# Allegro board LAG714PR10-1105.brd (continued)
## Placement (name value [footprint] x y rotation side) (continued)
PCG123  22U_0603_6.3V6M  [C_0603]  128.2 101.02 0 top
PCG124  22U_0603_6.3V6M  [C_0603]  126.74 101.12 180 top
PCG125  22U_0603_6.3V6M  [C_0603]  134.78 126.17 90 top
PCG126  22U_0603_6.3V6M  [C_0603]  122.56 90.89 270 top
PCG127  22U_0603_6.3V6M  [C_0603]  126.73 106.2 180 top
PCG128  22U_0603_6.3V6M  [C_0603]  123.83 93.31 270 top
PCG129  22U_0603_6.3V6M  [C_0603]  123.83 90.89 270 top
PCG130  22U_0603_6.3V6M  [C_0603]  130.3 89.59 180 top
PCG131  22U_0603_6.3V6M  [C_0603]  122.56 93.31 270 top
PCG132  22U_0603_6.3V6M  [C_0603]  128.2 103.56 0 top
PCG133  22U_0603_6.3V6M  [C_0603]  126.73 103.66 180 top
PCG134  0.47U_0201_6.3V6K  [C_0201]  127.07 90.54 90 top
PCG135  0.47U_0201_6.3V6K  [C_0201]  126.05 89.92 270 top
PCG136  0.47U_0201_6.3V6K  [C_0201]  124.75 95.97 180 top
PCG137  0.47U_0201_6.3V6K  [C_0201]  126.05 90.54 90 top
PCG138  1U_0201_6.3V6M  [C_0201]  130.58 99.91 0 top
PCG139  1U_0201_6.3V6M  [C_0201]  124.75 98.64 180 top
PCG140  1U_0201_6.3V6M  [C_0201]  124.75 97.31 180 top
PCG141  1U_0201_6.3V6M  [C_0201]  128.08 89.92 270 top
PCG142  1U_0201_6.3V6M  [C_0201]  127.07 89.92 270 top
PCG143  1U_0201_6.3V6M  [C_0201]  130.65 97.94 0 top
PCG144  1U_0201_6.3V6M  [C_0201]  131.69 93.59 0 top
PCG145  1U_0201_6.3V6M  [C_0201]  131.7 92.86 0 top
PCG146  1U_0201_6.3V6M  [C_0201]  128.11 90.54 90 top
PCG147  10U_0402_6.3V6M  [C_0402]  132.05 92.02 270 top
PCG148  10U_0402_6.3V6M  [C_0402]  133.89 95.23 90 top
PCG171  220U 2V Y D2  [C_D2]  135.29 122.21 90 bottom
PCG172  220U 2V Y D2  [C_D2]  133.23 117.79 0 bottom
PCH01  0.1U_0402_25V6  [C_0402]  175.07 56.23 90 bottom
PCH02  2200P_0402_50V7K  [C_0402]  174.18 56.23 90 bottom
PCH03  10U_0805_25V6K~D  [C_0805]  170.96 54.49 90 bottom
PCH04  10U_0805_25V6K~D  [C_0805]  170.96 54.49 90 top
PCH05  22U_0603_6.3V6M  [C_0603]  153.39 56.62 90 bottom
PCH06  22U_0603_6.3V6M  [C_0603]  154.59 56.62 90 bottom
PCH07  22U_0603_6.3V6M  [C_0603]  154.59 52.87 270 bottom
PCH08  22U_0603_6.3V6M  [C_0603]  153.39 52.87 270 bottom
PCH09  0.1U_0402_25V6  [C_0402]  170.51 53.48 0 top
PCH10  1U_0402_10V6K  [C_0402]  168.63 51.87 270 top
PCH11  1U_0402_10V6K  [C_0402]  166.79 51.87 270 bottom
PCH12  0.1U_0402_10V6K  [C_0402]  164.63 50.96 90 bottom
PCH13  680P_0603_50V7K  [C_0603]  167.17 55.49 0 top
PCH14  330P_0402_50V7K  [C_0402]  170.14 50.1 0 bottom
PCH15  1000P_0402_50V7K  [C_0402]  173.27 56.23 90 bottom
PCH16  1000P_0402_50V7K  [C_0402]  172.37 56.25 90 bottom
PCI01  10U_0805_25V6K  [C_0805]  164.5 74.17 270 bottom
PCI02  10U_0805_25V6K  [C_0805]  166.21 74.17 270 bottom
PCI03  10U_0805_25V6K  [C_0805]  164.5 74.17 270 top
PCI04  10U_0805_25V6K  [C_0805]  166.21 74.17 270 top
PCI05  1000P_0402_50V7K  [C_0402]  163.17 73.4 270 bottom
PCI06  0.1U_0402_25V6  [C_0402]  162.28 73.4 270 bottom
PCI07  2200P_0402_50V7K  [C_0402]  161.39 73.38 270 bottom
PCI08  1000P_0402_50V7K  [C_0402]  167.53 74.02 270 bottom
PCI09  0.22U_0603_25V7K  [C_0603]  165.71 75.8 180 bottom
PCI10  1U_0402_16V6K  [C_0402]  164.32 78.09 0 bottom
PCI11  1U_0402_16V6K  [C_0402]  165.13 79.87 270 bottom
PCI12  680P_0603_50V8J  [C_0603]  158.25 76.64 0 top
PCI13  33U_D2_25VM_R40M  [C_EEFCX1E330R]  163.99 83.58 270 bottom
PCI14  33U_25V_M  [C_6P3X4P5-NPM]  163.99 83.98 90 bottom
PCI21  0.1U_0402_25V6  [C_0402]  160.24 93.87 180 bottom
PCI22  2200P_0402_50V7K  [C_0402]  160.26 92.96 180 bottom
PCI23  10U_0805_25V6K  [C_0805]  161.68 93.51 0 bottom
PCI24  10U_0805_25V6K  [C_0805]  161.68 95.23 0 bottom
PCI25  10U_0805_25V6K  [C_0805]  161.68 93.51 0 top
PCI26  10U_0805_25V6K  [C_0805]  161.68 95.23 0 top
PCI27  1000P_0402_50V7K  [C_0402]  160.26 95.71 180 bottom
PCI28  1000P_0402_50V7K  [C_0402]  160.26 94.78 180 bottom
PCI29  0.22U_0603_25V7K  [C_0603]  164.31 97.26 180 bottom
PCI30  1U_0402_16V6K  [C_0402]  162.95 99.6 0 bottom
PCI31  1U_0402_16V6K  [C_0402]  163.8 101.39 270 bottom
PCI32  680P_0603_50V8J  [C_0603]  158.07 102.89 270 top
PCI101  22U_0603_6.3V6M  [C_0603]  125.99 82.39 0 top
PCI102  22U_0603_6.3V6M  [C_0603]  122.75 81.37 0 top
PCI103  22U_0603_6.3V6M  [C_0603]  130.15 80.02 270 top
PCI104  22U_0603_6.3V6M  [C_0603]  130.24 81.12 180 top
PCI105  22U_0603_6.3V6M  [C_0603]  128.93 80.02 270 top
PCI106  22U_0603_6.3V6M  [C_0603]  128.53 85.02 180 top
PCI107  22U_0603_6.3V6M  [C_0603]  130.05 76.99 270 top
PCI108  22U_0603_6.3V6M  [C_0603]  128.78 76.99 270 top
PCI109  22U_0603_6.3V6M  [C_0603]  124.27 83.02 90 top
PCI110  22U_0603_6.3V6M  [C_0603]  123 83.02 90 top
PCI111  22U_0603_6.3V6M  [C_0603]  127.71 80.02 270 top
PCI112  22U_0603_6.3V6M  [C_0603]  126.49 80.02 270 top
PCI113  22U_0603_6.3V6M  [C_0603]  125.27 80.02 270 top
PCI114  22U_0603_6.3V6M  [C_0603]  127.51 76.99 270 top
PCI115  22U_0603_6.3V6M  [C_0603]  124.97 76.99 270 top
PCI116  22U_0603_6.3V6M  [C_0603]  126.24 76.99 270 top
PCI117  22U_0603_6.3V6M  [C_0603]  122.75 78.83 0 top
PCI118  22U_0603_6.3V6M  [C_0603]  122.75 80.1 0 top
PCI119  22U_0603_6.3V6M  [C_0603]  149.58 87.74 0 top
PCI120  22U_0603_6.3V6M  [C_0603]  131.32 76.99 270 top
PCI121  22U_0603_6.3V6M  [C_0603]  126.05 85.43 90 top
PCI122  22U_0603_6.3V6M  [C_0603]  125.35 81.12 0 top
PCI123  22U_0603_6.3V6M  [C_0603]  123.76 77.69 270 top
PCI124  22U_0603_6.3V6M  [C_0603]  149.58 86.47 0 top
PCI125  22U_0603_6.3V6M  [C_0603]  122.56 77.69 270 top
PCI126  22U_0603_6.3V6M  [C_0603]  149.58 85.2 0 top
PCI127  22U_0603_6.3V6M  [C_0603]  149.58 89.02 0 top
PCI128  22U_0603_6.3V6M  [C_0603]  149.58 83.93 0 top
PCI129  1U_0201_6.3V6M  [C_0201]  128.08 80.82 90 top
PCI130  1U_0201_6.3V6M  [C_0201]  146.72 87.66 270 top
PCI131  1U_0201_6.3V6M  [C_0201]  132.27 79.43 90 top
PCI132  1U_0201_6.3V6M  [C_0201]  129.69 77.81 0 top
PCI133  1U_0201_6.3V6M  [C_0201]  122.05 83.43 90 top
PCI134  1U_0201_6.3V6M  [C_0201]  120.55 79.15 0 top
PCI135  1U_0201_6.3V6M  [C_0201]  146.08 91.22 270 top
PCI136  1U_0201_6.3V6M  [C_0201]  145.45 91.22 270 top
PCI137  1U_0201_6.3V6M  [C_0201]  147.35 87.66 270 top
PCI138  1U_0201_6.3V6M  [C_0201]  144.18 88.86 90 top
PCI139  1U_0201_6.3V6M  [C_0201]  120.48 78.33 270 top
PCI140  1U_0201_6.3V6M  [C_0201]  121.13 80.16 180 top
PCI141  1U_0201_6.3V6M  [C_0201]  126.46 77.81 0 top
PCI142  1U_0201_6.3V6M  [C_0201]  120.55 80.99 0 top
PCI143  1U_0201_6.3V6M  [C_0201]  128.04 77.81 0 top
PCI144  1U_0201_6.3V6M  [C_0201]  124.87 77.81 0 top
PCI145  1U_0201_6.3V6M  [C_0201]  144.18 87.66 270 top
PCI146  1U_0201_6.3V6M  [C_0201]  144.18 91.22 270 top
PCI147  1U_0201_6.3V6M  [C_0201]  144.18 94.74 270 top
PCI148  1U_0201_6.3V6M  [C_0201]  144.81 92.41 90 top
PCI149  1U_0201_6.3V6M  [C_0201]  145.45 87.66 270 top
PCI150  1U_0201_6.3V6M  [C_0201]  146.08 87.66 270 top
PCI151  1U_0201_6.3V6M  [C_0201]  144.81 87.66 270 top
PCI152  1U_0201_6.3V6M  [C_0201]  147.99 87.66 270 top
PCI153  1U_0201_6.3V6M  [C_0201]  146.72 88.86 90 top
PCI154  1U_0201_6.3V6M  [C_0201]  146.08 88.86 90 top
PCI155  1U_0201_6.3V6M  [C_0201]  145.45 88.86 90 top
PCI156  1U_0201_6.3V6M  [C_0201]  148.62 87.66 270 top
PCI157  1U_0201_6.3V6M  [C_0201]  133.51 81.3 90 top
PCI158  1U_0201_6.3V6M  [C_0201]  144.18 92.41 90 top
PCI159  1U_0201_6.3V6M  [C_0201]  144.81 88.86 90 top
PCI160  1U_0201_6.3V6M  [C_0201]  132.27 77.34 270 top
PCI161  1U_0201_6.3V6M  [C_0201]  133.49 77.37 0 top
PCI162  1U_0201_6.3V6M  [C_0201]  144.81 91.22 270 top
PCI163  1U_0201_6.3V6M  [C_0201]  127.51 80.82 90 top
PCI164  10U_0402_6.3V6M  [C_0402]  132.11 81.92 270 top
PCI165  10U_0402_6.3V6M  [C_0402]  132.11 82.79 90 top
PCI171  220U 2V Y D2  [C_D2]  152.47 90.15 0 bottom
PCI172  330U_D2_2V_Y  [C_D2]  145.96 95.28 90 bottom
PCI173  220U 2V Y D2  [C_D2]  148.05 90.76 270 bottom
PCM01  0.1U_0402_25V6  [C_0402]  96.59 139.63 270 bottom
PCM02  2200P_0402_50V7K  [C_0402]  95.7 139.63 270 bottom
PCM03  4.7U_0805_25V6K  [C_0805]  94.3 140.53 270 top
PCM04  4.7U_0805_25V6K  [C_0805]  94.3 140.53 270 bottom
PCM05  22U_0603_6.3V6M  [C_0603]  83.92 131.5 180 top
PCM06  22U_0603_6.3V6M  [C_0603]  83.92 130.23 180 top
PCM07  22U_0603_6.3V6M  [C_0603]  87.73 131.5 0 top
PCM08  22U_0603_6.3V6M  [C_0603]  83.92 131.5 180 bottom
PCM09  22U_0603_6.3V6M  [C_0603]  87.73 131.5 0 bottom
PCM10  22U_0603_6.3V6M  [C_0603]  83.92 130.23 180 bottom
PCM11  680P_0402_50V7K  [C_0402]  90.51 138.87 0 top
PCM12  0.1U_0402_10V7K  [C_0402]  93.13 136.6 270 bottom
PCM13  1U_0603_10V6K  [C_0603]  91.6 132.65 180 bottom
PCM14  1U_0603_10V6K  [C_0603]  91.6 131.42 180 bottom
PCM15  0.1U_0402_10V7K  [C_0402]  95.47 129.61 270 bottom
PCM16  0.1U_0402_10V7K  [C_0402]  96.36 129.61 270 bottom
PCM17  220P_0402_25V8J  [C_0402]  98.52 129.78 90 bottom
PCM18  .1U_0402_16V7K  [C_0402]  98.51 131.57 0 bottom
PCM19  0.033U_0402_16V7K  [C_0402]  98.51 132.52 0 bottom
PCM20  10U_0603_6.3V6M  [C_0603]  98.9 133.76 90 top
PCM21  10U_0603_6.3V6M  [C_0603]  98.87 134.08 90 bottom
PCM22  1000P_0402_50V7K  [C_0402]  96.59 139.63 270 top
PCM23  1000P_0402_50V7K  [C_0402]  95.7 139.63 270 top
PCZ01  8200P_0402_25V7K  [C_0402]  155.85 114.98 0 top
PCZ02  2200P_0402_50V7K  [C_0402]  158.53 115.6 90 bottom
PCZ03  15P_0402_50V8J  [C_0402]  155.85 115.87 0 top
PCZ04  1000P_0402_50V7K  [C_0402]  156.76 112.82 180 bottom
PCZ05  1000P_0402_50V7K  [C_0402]  154.42 115.61 180 top
PCZ06  1000P_0402_50V7K  [C_0402]  157.67 112.81 90 bottom
PCZ07  2200P_0402_25V7K  [C_0402]  156.76 114.6 180 bottom
PCZ08  0.01U_0402_25V7K  [C_0402]  155.86 115.6 90 bottom
PCZ09  1200P_0402_50V7K  [C_0402]  156.75 115.6 90 bottom
PCZ10  1000P_0402_50V7K  [C_0402]  155.28 110.98 0 bottom
PCZ11  3300P_0402_25V7K  [C_0402]  156.18 110.07 90 top
PCZ12  470P_0402_50V7K  [C_0402]  154.42 116.5 180 top
PCZ13  470P_0402_50V7K  [C_0402]  153.39 107.92 90 bottom
PCZ14  470P_0402_50V7K  [C_0402]  151.86 111.47 90 top
PCZ15  15P_0402_50V8J  [C_0402]  153.4 109.71 180 top
PCZ16  2200P_0402_50V7K  [C_0402]  152.5 107.92 90 top
PCZ17  820P_0402_50V7K  [C_0402]  151.62 109.71 180 bottom
PCZ18  100P_0402_50V8J  [C_0402]  151.62 108.82 180 bottom
PCZ19  0.1U_0402_25V6  [C_0402]  150.47 111.47 90 top
PCZ20  0.1U_0402_25V6  [C_0402]  149.84 109.71 180 top
PCZ21  0.1U_0402_25V6  [C_0402]  149.84 108.82 180 bottom
PCZ22  1000P_0402_50V7K  [C_0402]  149.13 111.47 90 top
PCZ23  0.01U_0402_50V7K  [C_0402]  147.35 110.54 270 bottom
PCZ24  0.1U_0402_25V6  [C_0402]  154.59 120.04 90 top
PCZ25  470P_0402_50V7K  [C_0402]  151.04 118.74 270 top
PCZ26  0.022U_0402_16V7K  [C_0402]  150.03 120.06 180 top
PCZ27  5600P_0402_25V7K  [C_0402]  150.03 120.03 180 bottom
PCZ28  3300P_0402_50V7-K  [C_0402]  146.15 118.14 90 bottom
PCZ29  1000P_0402_50V7K  [C_0402]  146.47 120.26 270 top
PCZ30  150P_0402_50V8J  [C_0402]  147.18 121.22 180 top
PCZ31  0.015U_0402_25V7K  [C_0402]  148.12 120.38 90 top
PCZ32  1000P_0402_50V7K  [C_0402]  149.26 118.74 270 top
PCZ33  2200P_0402_50V7K  [C_0402]  150.15 118.74 270 top
PCZ34  1U_0603_10V6K  [C_0603]  145.64 112.25 180 bottom
PCZ35  1000P_0402_50V7K  [C_0402]  144.67 117.58 0 top
PCZ36  1000P_0402_50V7K  [C_0402]  145.59 116.69 180 top
PD1  -  [TVNST52302AB0_SOT523-3]  82.08 143.38 180 top
PD2  -  [BAV99W_SC70-3]  89.28 148.25 0 top
PD3  -  [BAV99W_SC70-3]  90.61 143.29 180 top
PD5  -  [TVNST52302AB0_SOT523-3]  161.83 36.32 180 top
PD6  -  [TVNST52302AB0_SOT523-3]  167.29 38.35 0 top
PD501  -  [SDMK0340L-7-F_SOD323-2]  116.17 142.04 180 bottom
PDB01  -  [LRB715FT1G_SOT323-3]  193.78 43.87 90 bottom
PHZ01  100K_0402_1%_B25/50 4250K  [R_0402]  158.53 65.32 90 bottom
PHZ02  220K_0402_5%_B25/50 4700K  [R_0402]  151.04 81.02 270 bottom
PHZ03  100K_0402_1%_B25/50 4250K  [R_0402]  143.24 120.96 180 bottom
PHZ04  100K_0402_1%_B25/50 4250K  [R_0402]  161.21 80.81 180 bottom
PHZ05  100K_0402_1%_B25/50 4250K  [R_0402]  138.53 136.15 270 bottom
PJP1  JUMP_43X79  [JUMP_43X79-NPM]  95.47 144.96 0 top
PJP2  -  [JUMP_43X79]  76.24 145.17 180 bottom
PJP3  JUMP_43X79  [JUMP_43X79-NPM]  176.21 45.23 180 bottom
PJP301  -  [JUMP_43X39]  101.05 140.01 0 bottom
PJP302  -  [JUMP_43X118]  115.83 131.44 270 top
PJP501  -  [JUMP_43X79]  152.84 142.7 270 top
PJP502  -  [JUMP_43X118]  158.28 124.18 270 bottom
PJP1801  -  [JUMP_43X39]  171.03 45.43 90 top
PJP1802  -  [JUMP_43X79]  153.49 46.65 180 bottom
PJP2501  -  [JUMP_43X39]  48.73 26.1 0 bottom
PJP2502  -  [JUMP_43X39]  52.74 36.71 90 top
PJPA01  -  [JUMP_43X39]  167.04 68.33 270 bottom
PJPB01  JUMP_43X118  [JUMP_43X118-NPM]  186.81 55.68 0 bottom
PJPDC1  ACES_50458-00601-001  [ACES_50458-00601-001_6P-T]  81.2 144.15 0 bottom
PJPG01  -  [JUMP_43X79]  142.12 142.24 270 top
PJPH01  -  [JUMP_43X39]  177.4 56.89 180 bottom
PJPH02  -  [JUMP_43X118]  154.34 56.28 90 top
PJPI01  JUMP_43X79  [JUMP_43X79-NPM]  170 81.34 180 bottom
PJPM01  -  [JUMP_43X39]  97.76 141.16 180 top
PJPM02  -  [JUMP_43X118]  87.03 129.51 270 bottom
PJPM03  -  [JUMP_43X39]  98.97 132.34 270 top
PL1  5A Z150 20M 1210_2P  [5A_Z150_1210_2P]  94.65 144.86 0 top
PL2  5A Z150 20M 1210_2P  [5A_Z150_1210_2P-NPM]  77.05 145.17 180 bottom
PL3  BLM15AG102SN1D_2P  [MURAT_BLM15AG102SN1D_2P]  84.41 144.71 180 top
PL4  5A Z150 20M 1210_2P  [5A_Z150_1210_2P]  177.05 45.17 180 bottom
PL301  1.5UH_9A_20%_7X7X3_M  [L_7X7X3_M_2P]  106.09 132.99 0 bottom
PL311  5A Z80 20M 0805  [TAI-T_HCB2012KF-121T50_2P]  100.66 137.98 0 bottom
PL501  1.5UH_9A_20%_7X7X3_M  [L_7X7X3_M_2P]  158.28 133.44 270 bottom
PL511  5A Z150 20M 1210_2P  [5A_Z150_1210_2P]  149.21 142.68 270 top
PL1801  1UH_6.6A_20%_5X5X3_M  [L_5X5X3_M_2P]  161.98 46.78 180 bottom
PL1811  5A_Z120_25M_0805_2P  [TAI-T_HCB2012KF-121T50_2P]  171.2 44.89 90 bottom
PLA01  0.47UH_MMD05CZR47M_12A_20%  [L_5X5X3_M]  162.04 61.95 180 bottom
PLB01  4.7UH_5.5A_20%_7X7X3_M  [L_7X7X3_M_2P]  182.11 43.81 90 bottom
PLB02  5A Z150 20M 1210_2P  [5A_Z150_1210_2P]  186.01 55.68 0 bottom
PLG01  0.15UH_MMD-06DZER15MEM1L__36A_20%  [L_7X7X4_M]  145.7 125.21 180 bottom
PLG11  5A Z150 20M 1210_2P  [5A_Z150_1210_2P]  145.75 142.68 270 top
PLH01  1UH_11A_20%_7X7X3_M  [L_7X7X3_M_2P]  163.18 54.84 180 bottom
PLH11  5A Z80 20M 0805  [TAI-T_HCB2012KF-121T50_2P]  177.36 54.87 180 bottom
PLI01  0.15UH_MMD-06DZER15MEM1L__36A_20%  [L_7X7X4_M]  158.49 83.98 180 bottom
PLI02  0.15UH_MMD-06DZER15MEM1L__36A_20%  [L_7X7X4_M]  152.12 100.79 270 bottom
PLI11  5A Z150 20M 1210_2P  [5A_Z150_1210_2P]  170.8 81.34 180 bottom
PLM01  1UH_11A_20%_7X7X3_M  [L_7X7X3_M_2P]  85.92 134.08 90 bottom
PLM11  5A Z80 20M 0805  [TAI-T_HCB2012KF-121T50_2P]  98.03 140.96 180 bottom
PQ1  -  [FDV301N-G_SOT23-3]  82.58 147.26 270 top
PQ2  -  [MMST3904-7-F_SOT323-3]  87.18 143.2 0 top
PQ11  2N7002KW_SOT323-3  [DMN65D8LW-7_SOT323-3]  27.02 60.38 90 top
PQ12  2N7002KDW_SOT363-6  [DMN65D8LDW-7_SOT363-6]  118.12 142.52 180 top
PQ13  2N7002KDW_SOT363-6  [DMN65D8LDW-7_SOT363-6]  120.35 140.03 0 top
PQA01  PE642DT_PDFN8-10  [AON7934_DFN3X3A8-10]  164.67 64.03 0 bottom
PQB01  AON7408L_DFN8-5  [AON7702L_DFN8-5]  186.64 49.25 90 bottom
PQB02  AON7506_DFN33-8-5  [AON7702L_DFN8-5]  189.51 47.4 270 bottom
PQB03  2N7002KW_SOT323-3  [DMN65D8LW-7_SOT323-3]  181.3 66.43 90 top
PQB04  2N7002KW_SOT323-3  [DMN65D8LW-7_SOT323-3]  204.32 56.95 90 top
PQB05  -  [RUM002N02GT2L_VMT3]  205.33 49.36 270 top
PQB06  -  [RUM002N02GT2L_VMT3]  206.67 47.62 270 top
PQB07  -  [LTC015EUBFS8TL_UMT3F]  175.42 35.71 180 top
PQB08  -  [LMUN5113T1G_SOT323-3]  171.55 36.38 270 top
PQB11  -  [TPCA8059-H_PPAK56-8-5]  180.2 59.63 90 top
PQB12  -  [TPCA8059-H_PPAK56-8-5]  181.96 62.25 270 top
PQB13  -  [TPCA8059-H_PPAK56-8-5]  183.76 52.76 180 bottom
PQM01  PE642DT_PDFN8-10  [AON7934_DFN3X3A8-10]  90.68 141.42 0 bottom
PR1  33_0402_5%  [R_0402]  86.72 148.22 0 top
PR3  100K_0402_1%  [R_0402]  86.72 147.26 0 top
PR4  10K_0402_1%  [R_0402]  88.93 145.17 270 top
PR5  2.2K_0402_5%  [R_0402]  87.64 149.17 180 top
PR6  15K_0402_1%  [R_0402]  87.64 146.31 180 top
PR7  100K_0402_1%  [R_0402]  88.35 142.93 0 top
PR31  0_0402_5%  [R_0402]  121.95 138.16 90 top
PR32  3.3K_1206_5%  [R_1206]  123.35 142.88 270 top
PR33  10K_0402_1%  [R_0402]  118.87 138.77 90 top
PR34  1M_0402_1%  [R_0402]  121.78 143.84 180 top
PR35  0_0402_5%  [R_0402]  120.23 138.18 0 top
PR36  1M_0402_1%  [R_0402]  118.41 143.82 180 top
PR37  100_0402_5%  [R_0402]  163.23 37.85 270 top
PR38  1M_0402_1%  [R_0402]  120.86 142.95 0 top
PR39  200_0402_5%  [R_0402]  164.88 37.85 270 top
PR40  100K_0402_1%  [R_0402]  117.1 139.67 180 top
PR41  10K_0402_1%  [R_0402]  165.77 36.94 90 top
PR42  100_0402_5%  [R_0402]  160.44 37.85 270 top
PR43  100K_0402_1%  [R_0402]  30.13 59.8 90 top
PR44  1M_0402_1%  [R_0402]  115.85 143.82 0 top
PR45  1M_0402_1%  [R_0402]  121.14 139.07 180 top
PR301  0_0603_5%  [R0603_0OHM]  104.69 137.49 270 bottom
PR302  499K_0402_1%  [R_0402]  109.25 142.48 90 bottom
PR303  150K_0402_1%  [R_0402]  110.14 142.48 90 bottom
PR304  10K_0402_1%  [R_0402]  109.58 141.03 180 top
PR305  4.7_1206_5%  [R_1206]  106.71 135.38 90 top
PR306  1K_0402_5%  [R_0402]  113.03 138.5 180 bottom
PR307  150K_0402_1%  [R_0402]  111.24 138.48 90 bottom
PR308  150K_0402_1%  [R_0402]  112.11 140.28 0 bottom
PR501  0_0603_5%  [R0603_0OHM]  155.18 137.1 270 bottom
PR502  0_0402_5%  [R0402_0OHM]  111.46 141.21 0 bottom
PR503  0_0402_5%  [R0402_0OHM]  161.39 139.11 90 bottom
PR504  10K_0402_1%  [R_0402]  158.94 141.86 270 bottom
PR505  4.7_1206_5%  [R_1206]  156.88 133.85 90 top
PR506  2.2K_0402_5%  [R_0402]  163.18 140.08 180 bottom
PR507  0_0402_5%  [R0402_0OHM]  115.27 143.31 0 bottom
PR508  1M_0402_5%  [R_0402]  112.38 142.93 180 bottom
PR509  1K_0402_5%  [R_0402]  163.19 137.44 180 bottom
PR510  150K_0402_1%  [R_0402]  161.4 137.41 90 bottom
PR511  150K_0402_1%  [R_0402]  162.28 139.15 0 bottom
PR1801  0_0402_5%  [R0402_0OHM]  166.8 49.38 180 top
PR1802  1M_0402_5%  [R_0402]  165.88 49.38 0 bottom
PR1803  100K_0402_5%  [R_0402]  164.75 48.61 270 top
PR1804  4.7_1206_5%  [R_1206]  162.21 48.17 270 top
PR1805  10K_0402_1%  [R_0402]  168.46 49.38 180 bottom
PR1807  20K_0402_1%  [R_0402]  170.16 48.24 180 bottom
PR2501  0_0402_5%  [R0402_0OHM]  57.21 27.62 180 bottom
PR2502  21.5K_0402_1%  [R_0402]  53.65 36.22 0 bottom
PR2503  10K_0402_1%  [R_0402]  55.36 36.07 270 bottom
PR2504  2.2_0402_1%  [R_0402]  49.95 30.61 270 bottom
PRA01  2.2_0603_5%  [R_0603]  171.74 62.78 180 bottom
PRA02  4.7_1206_5%  [R_1206]  162.21 62.97 270 top
PRB01  0.01_1206_1%  [R_1206_4P]  177.01 52.67 270 bottom
PRB02  0.01_1206_1%  [R_1206_4P]  187.61 56.29 180 top
PRB03  3M_0402_5%  [R_0402]  183.6 63.81 90 top
PRB04  0_0402_5%  [R_0402]  179.7 58.07 0 top
PRB05  0_0402_5%  [R0402_0OHM]  202.22 56.14 270 bottom
PRB06  2_0402_5%  [R_0402]  201.33 56.14 270 bottom
PRB07  4.02K_0402_1%  [R_0402]  179.85 66.12 180 top
PRB08  4.02K_0402_1%  [R_0402]  182.81 63.8 90 top
PRB09  392K_0402_1%  [R_0402]  204.96 55.24 180 top
PRB10  100_0402_1%  [R_0402]  198.64 55.32 270 bottom
PRB11  53.6K_0402_1%  [R_0402]  204.05 54.35 0 bottom
PRB12  0_0603_5%  [R0603_0OHM]  181.39 53.84 180 top
PRB13  100K_0402_1%  [R_0402]  204.96 53.27 180 bottom
PRB14  158K_0402_1%  [R_0402]  204.05 53.27 0 top
PRB15  0_0603_5%  [R0603_0OHM]  196.63 53.91 180 bottom
PRB16  0_0603_5%  [R_0603]  196.63 52.64 180 bottom
PRB17  0_0402_5%  [R0402_0OHM]  204.96 52.38 180 bottom
PRB18  0_0402_5%  [R0402_0OHM]  204.96 51.49 180 bottom
PRB19  0_0402_5%  [R_0402]  204.96 50.6 180 bottom
PRB20  1K_0402_1%  [R_0402]  204.96 49.72 180 bottom
PRB21  4.7_0402_5%  [R_0402]  196.41 49.44 90 bottom
PRB22  4.7_1206_5%  [R_1206]  186.53 49.4 270 top
PRB23  0_0402_5%  [R0402_0OHM]  204.96 48.83 180 bottom
PRB24  10.5K_0402_1%  [R_0402]  204.05 47.94 0 bottom
PRB25  100K_0402_1%  [R_0402]  197.65 46.43 270 bottom
PRB26  0_0402_5%  [R0402_0OHM]  197.63 45.52 0 top
PRB27  10_1206_5%  [R_1206]  193.77 46.16 0 bottom
PRB28  0_0603_5%  [R_0603]  172.06 38.29 0 top
PRB29  10K_0402_5%  [R_0402]  204.96 50.6 180 top
PRB30  10K_0402_5%  [R_0402]  203.68 46.27 90 top
PRB31  160K_0402_1%  [R_0402]  203.79 47.95 0 top
PRB32  200K_0402_1%  [R_0402]  198.14 48.71 270 top
PRB33  200K_0402_1%  [R_0402]  199 48.71 0 top
PRB34  2_0402_5%  [R_0402]  199.3 45.51 90 bottom
PRB35  75K_0402_1%  [R_0402]  198.47 46.43 270 bottom
PRB36  66.5K_0402_1%  [R_0402]  200.77 48.71 0 top
PRB37  182K_0402_1%  [R_0402]  203.45 46.43 0 bottom
PRB38  100_0402_1%  [R_0402]  202.6 46.43 270 bottom
PRB39  102K_0402_1%  [R_0402]  201.81 46.44 270 bottom
PRB40  10K_0402_1%  [R_0402]  200.85 45.52 90 bottom
PRB41  0_0402_5%  [R0402_0OHM]  200.07 45.51 90 bottom
PRB42  10K_0402_1%  [R_0402]  200.94 45.52 0 top
PRB43  1M_0402_1%  [R_0402]  184.36 64.52 0 top
PRC01  0.0002_0805_5%  [R_0805]  124.46 85.56 90 top
PRC02  0.0002_0805_5%  [R_0805]  130.01 88.32 270 top
PRC03  0.0002_0805_5%  [R_0805]  129.99 83.49 90 top
PRC04  SOLDER_0603  [SOLDER_PREFORMS_0603-NPM]  124.49 85.75 90 top
PRC05  SOLDER_0603  [SOLDER_PREFORMS_0603-NPM]  129.98 88.13 270 top
PRC06  SOLDER_0603  [SOLDER_PREFORMS_0603-NPM]  130.02 83.61 90 top
PRC7  0.0002_0805_5%  [R_0805]  121.1 90.7 270 top
PRG01  3.9_0603_1%  [R_0603]  139.42 132.52 180 bottom
PRG02  2_0402_1%  [R_0402]  139.46 129.49 90 bottom
PRG03  4.7_1206_5%  [R_1206]  145.98 128.52 90 top
PRH01  0_0402_5%  [R0402_0OHM]  171.43 52.61 180 top
PRH02  1M_0402_1%  [R_0402]  170.52 53.46 0 bottom
PRH03  0_0402_5%  [R_0402]  167.67 50.96 90 top
PRH04  0_0402_5%  [R_0402]  166.79 51.87 270 top
PRH05  100K_0402_5%  [R_0402]  169.58 50.97 90 top
PRH06  10_0603_5%  [R_0603]  165.71 52.3 270 bottom
PRH07  4.7_1206_5%  [R_1206]  163.29 55.67 0 top
PRH08  21.5K_0402_1%  [R_0402]  169.52 51.87 270 bottom
PRH09  31.6K_0402_1%  [R_0402]  168.63 51.87 270 bottom
PRH11  2.2_0402_1%  [R_0402]  167.67 50.96 90 bottom
PRH12  1K_0402_1%  [R_0402]  170.4 50.96 90 bottom
PRI01  3.9_0603_1%  [R_0603]  164.31 77 0 bottom
PRI02  2_0402_1%  [R_0402]  164.25 79.87 270 bottom
PRI03  4.7_1206_5%  [R_1206]  156.79 79.37 270 top
PRI21  3.9_0603_1%  [R_0603]  162.96 98.47 0 bottom
PRI22  2_0402_1%  [R_0402]  162.91 101.39 270 bottom
PRI23  4.7_1206_5%  [R_1206]  154.02 102.29 0 top
PRM01  4.7_1206_5%  [R_1206]  86.71 138.36 0 top
PRM02  2.2_0603_5%  [R_0603]  95.47 136.57 180 bottom
PRM03  15.4K_0402_1%  [R_0402]  91.61 133.73 180 bottom
PRM04  5.1_0603_5%  [R_0603]  90.2 131.42 0 top
PRM05  2.2_0603_5%  [R_0603]  91.6 132.65 180 top
PRM06  10K_0402_1%  [R_0402]  92.77 128.7 90 bottom
PRM07  453K_0402_1%  [R_0402]  93.56 128.7 90 bottom
PRM08  0_0402_5%  [R0402_0OHM]  94.53 128.7 90 bottom
PRM09  0_0402_5%  [R0402_0OHM]  97.25 128.7 90 bottom
PRM10  6.04K_0402_1%  [R_0402]  99.41 129.78 90 bottom
PRM11  10K_0402_1%  [R_0402]  98.51 128.9 0 bottom
PRZ01  1.5K_0402_1%  [R_0402]  157.64 114.96 90 top
PRZ03  0_0402_5%  [R0402_0OHM]  157.65 112.82 180 top
PRZ04  1.78K_0402_1%  [R_0402]  156.76 111.93 180 bottom
PRZ05  18.2K_0402_1%  [R_0402]  154.42 114.72 180 top
PRZ06  10_0402_5%  [R_0402]  157.64 116.51 270 bottom
PRZ07  0_0402_5%  [R0402_0OHM]  157.65 113.71 180 top
PRZ08  1K_0402_1%  [R_0402]  156.76 113.71 180 bottom
PRZ10  12K_0402_1%  [R_0402]  156.76 117.77 180 top
PRZ11  20K_0402_1%  [R_0402]  153.18 113.77 0 top
PRZ13  7.5K_0603_1%  [R_0603]  158.02 118.85 180 top
PRZ14  0_0402_5%  [R0402_0OHM]  155.29 109.19 90 bottom
PRZ15  54.9K_0402_1%  [R_0402]  154.42 117.39 180 top
PRZ16  10K_0402_1%  [R_0402]  156.76 117.77 180 bottom
PRZ18  0_0402_5%  [R0402_0OHM]  156.18 109.19 90 bottom
PRZ19  1K_0402_1%  [R_0402]  155.29 110.07 90 top
PRZ20  49.9_0402_1%  [R_0402]  154.28 108.83 270 bottom
PRZ21  619_0402_1%  [R_0402]  154.29 109.71 180 bottom
PRZ22  0_0402_5%  [R0402_0OHM]  155.85 118.66 0 bottom
PRZ23  26.1K_0402_1%  [R_0402]  152.75 111.47 90 top
PRZ24  4.75K_0402_1%  [R_0402]  153.39 108.83 270 top
PRZ25  66.5K_0603_1%  [R_0603]  148.43 106.47 90 bottom
PRZ26  165K_0402_1%  [R_0402]  150.72 108.83 270 top
PRZ27  75K_0402_1%  [R_0402]  151.6 107.93 0 bottom
PRZ28  9.76K_0402_1%  [R_0402]  152.5 108.8 90 bottom
PRZ29  66.5K_0603_1%  [R_0603]  149.64 106.47 90 bottom
PRZ30  10_0402_1%  [R_0402]  149.01 101.88 90 bottom
PRZ31  10_0402_1%  [R_0402]  154.78 88.23 90 top
PRZ32  10K_0402_1%  [R_0402]  149.84 109.71 180 bottom
PRZ33  10K_0402_1%  [R_0402]  149.84 108.82 180 top
PRZ34  0_0402_5%  [R0402_0OHM]  147.34 111.48 0 top
PRZ35  1K_0402_1%  [R_0402]  146.47 109.63 90 bottom
PRZ36  61.9K_0402_1%  [R_0402]  147.34 112.37 0 top
PRZ37  2.15K_0402_1%  [R_0402]  148.05 107.03 90 top
PRZ38  2.15K_0402_1%  [R_0402]  148.94 107.03 90 top
PRZ39  1K_0402_1%  [R_0402]  149.83 107.03 90 top
PRZ40  45.3_0402_1%  [R_0402]  153.7 120.04 90 top
PRZ41  110_0402_1%  [R_0402]  152.82 120.04 90 top
PRZ42  100_0402_1%  [R_0402]  151.93 120.04 90 top
PRZ43  110_0402_1%  [R_0402]  151.04 120.04 90 top
PRZ44  7.5K_0603_1%  [R_0603]  149.7 122.41 270 top
PRZ45  12K_0402_1%  [R_0402]  147.34 120.96 0 bottom
PRZ46  49.9_0402_1%  [R_0402]  153.7 120.04 90 bottom
PRZ47  0_0402_5%  [R0402_0OHM]  152.82 120.04 90 bottom
PRZ48  10_0402_1%  [R_0402]  151.93 120.04 90 bottom
PRZ49  100_0402_1%  [R_0402]  151.04 120.04 90 bottom
PRZ50  95.3K_0402_1%  [R_0402]  151.93 118.74 270 top
PRZ51  10_0402_5%  [R_0402]  147.34 120.07 0 bottom
PRZ52  1K_0402_1%  [R_0402]  145.26 118.14 90 bottom
PRZ53  0_0402_5%  [R0402_0OHM]  145.59 120.25 180 top
PRZ55  2.15K_0402_1%  [R_0402]  148.13 122.17 180 top
PRZ56  52.3K_0402_1%  [R_0402]  148.37 118.74 270 top
PRZ57  2_0402_1%  [R_0402]  144.67 111.17 0 bottom
PRZ58  4.22K_0402_1%  [R_0402]  146.47 118.48 270 top
PRZ59  0_0402_5%  [R0402_0OHM]  144.67 119.36 0 top
PRZ60  24K_0402_1%  [R_0402]  145.59 114.21 180 bottom
PRZ61  3.65K_0402_1%  [R_0402]  145.59 118.47 180 top
PRZ63  0_0402_5%  [R0402_0OHM]  145.58 115.82 270 top
PRZ64  24K_0402_1%  [R_0402]  145.59 113.33 180 bottom
PRZ65  61.9K_0402_1%  [R_0402]  144.69 114.9 90 top
PRZ66  51.1K_0402_1%  [R_0402]  147.34 114.28 0 top
PRZ67  97.6K_0402_1%  [R_0402]  145.59 115.17 180 bottom
PRZ68  19.1K_0402_1%  [R_0402]  145.59 116.06 180 bottom
PRZ69  35.7K_0402_1%  [R_0402]  145.59 116.95 180 bottom
PU301  -  [SY8286BRAC_QFN20_3X3]  106.38 138.49 0 bottom
PU501  -  [SY8288CRAC_QFN20_3X3]  156.69 136.95 0 bottom
PU1801  -  [RT8061AZQW_WDFN10_3X3]  164.73 46.1 90 bottom
PU2501  -  [RT9059GSP_SO8]  54.96 28.33 180 bottom
PUA01  -  [NCP81253MNTBG_DFN8_2X2]  170.81 61.56 270 bottom
PUB01  ISL88739AHRZ-T_QFN32_4X4  [ISL95520HRZ-T_QFN32_4X4-S]  202.43 52.06 180 bottom
PUG01  -  [NCP302045MNTXG_PQFN33_5X5]  140.87 130.48 90 bottom
PUH01  -  [RT6226AGQUF_UQFN12_3X3]  166.04 54.73 0 bottom
PUI01  -  [NCP302045MNTXG_PQFN33_5X5]  162.77 78.75 270 bottom
PUI02  -  [NCP302045MNTXG_PQFN33_5X5]  161.58 101.04 270 bottom
PUM01  -  [RT8207PGQW_WQFN20_3X3]  96.64 133.57 270 bottom
PUZ01  -  [NCP81218MNTXG_QFN48_6X6]  153.01 112.05 90 bottom
Q1  -  [2N7002K_SOT23-3]  111.86 40.19 90 top
Q4  -  [L2N7002WT1G_SC-70-3]  53.45 51.53 0 top
Q6  -  [LN2306LT1G_SOT23-3]  80.01 38.42 270 bottom
Q7  -  [DDTA144VCA-7-F_SOT23-3]  83.54 36.73 180 bottom
Q8  -  [LN2306LT1G_SOT23-3]  90.2 32.5 180 top
Q9  -  [LN2306LT1G_SOT23-3]  109.25 28.13 180 top
Q10  L2N7002DW1T1G 2N SC88-6  [DMN66D0LDW-7_SOT363-6]  121.72 28.49 180 top
Q11  L2N7002DW1T1G 2N SC88-6  [DMN66D0LDW-7_SOT363-6]  106.62 128.5 270 bottom
Q12  NTK3139PT1G_SOT723-3  [2N7002K_SOT23-3]  101.25 28.13 180 top
Q13  -  [2N7002K_SOT23-3]  105.25 28.13 180 top
Q14  -  [LMBT3904LT1G_SOT23-3]  153.16 124.9 270 bottom
Q15  LP2301ALT1G 1P SOT-23-3  [SI2301CDS-T1-GE3_SOT23-3]  50.12 48.8 0 top
Q17  L2N7002DW1T1G 2N SC88-6  [DMN66D0LDW-7_SOT363-6]  19.15 120.53 270 bottom
Q18  -  [DDTA144VCA-7-F_SOT23-3]  13.22 119.57 90 bottom
Q19  -  [DDTA144VCA-7-F_SOT23-3]  13.22 123.63 90 bottom
Q22  -  [LN2306LT1G_SOT23-3]  18.04 123.63 90 bottom
Q23  -  [LP2301ALT1G_SOT23-3]  60.45 29.65 90 top
Q24  -  [L2N7002WT1G_SC-70-3]  56.04 28 270 top
Q25  L2N7002DW1T1G 2N SC88-6  [DMN66D0LDW-7_SOT363-6]  26.72 121.41 90 bottom
QA1  -  [LN2306LT1G_SOT23-3]  40.42 26.37 180 top
QC1  L2N7002DW1T1G 2N SC88-6  [DMN66D0LDW-7_SOT363-6]  131.06 54.43 90 top
QC2  -  [2N7002K_SOT23-3]  90.81 36.89 270 bottom
QI1  -  [2N7002K_SOT23-3]  22.28 105.09 90 top
QI2  L2N7002DW1T1G 2N SC88-6  [DMN66D0LDW-7_SOT363-6]  23.15 105.24 90 bottom
QI3  2N7002KW_SOT323-3  [DMN65D8LW-7_SOT323-3]  21.37 104.62 0 bottom
QS1  L2N7002DW1T1G 2N SC88-6  [DMN66D0LDW-7_SOT363-6]  188.06 36.14 270 top
R1  1K_0402_5%  [R_0402]  106.97 39.63 270 top
R2  10M_0402_5%  [R_0402]  107.86 39.63 270 top
R3  0_0805_5%  [R_0805]  216.86 56.18 0 top
R4  0_0603_5%  [R_0603]  212.19 30.79 0 top
R5  10K_0402_5%  [R_0402]  212.11 54.72 0 top
R6  0_0402_5%  [R0402_0OHM]  213.03 53.83 180 top
R7  0_0603_5%  [R_0603]  212.19 32.06 0 top
R8  0_0402_5%  [R0402_0OHM]  217.83 53.83 0 top
R9  0_0402_5%  [R_0402]  220.58 53.83 180 top
R10  100K_0402_5%  [R_0402]  223.17 58.26 90 top
R11  0_0603_5%  [R_0603]  221.14 47.35 0 top
R12  0_0603_5%  [R_0603]  221.46 42.36 180 top
R13  0_0603_5%  [R_0603]  218.03 42.36 180 top
R16  0_0603_5%  [R_0603]  219.62 47.35 180 top
R17  0_0402_5%  [R_0402-NPM]  210.79 46.45 90 bottom
R18  0_0402_5%  [R_0402-NPM]  209.9 46.45 90 bottom
R19  33_0402_5%  [R_0402]  215.05 41.62 90 top
R20  0_0402_5%  [R_0402]  210.09 40.25 270 bottom
R21  0_0402_5%  [R_0402]  210.98 40.25 270 bottom
R22  100_0402_5%  [R_0402]  218.67 61.61 0 top
R23  10K_0402_5%  [R_0402]  21.88 123.68 90 bottom
R24  100K_0402_5%  [R_0402]  76.3 37.96 90 bottom
R25  1K_0402_5%  [R_0402]  82.03 35.87 180 bottom
R26  51K_0402_5%  [R_0402]  93.63 31.64 90 top
R27  100K_0402_5%  [R_0402]  93.63 30.71 270 top
R28  18.7K_0402_1%  [R_0402]  109.64 127.64 270 bottom
R29  2K_0402_1%  [R_0402]  101.51 128.15 270 bottom
R30  10K_0402_5%  [R_0402]  211.97 47.28 180 top
R31  4.7K_0402_5%  [R_0402]  126.27 27.72 90 top
R32  4.7K_0402_5%  [R_0402]  127.22 27.72 90 top
R33  4.7K_0402_5%  [R_0402]  117.45 26.58 0 top
R34  4.7K_0402_5%  [R_0402]  122.78 27.59 90 top
R35  0_0402_5%  [R_0402]  98.4 28.06 270 top
R36  0_0603_5%  [R_0603]  100.94 31.43 270 top
R37  100_0603_5%  [R_0603]  107.29 30.01 0 top
R38  20K_0402_1%  [R_0402]  97.51 26.22 270 top
R39  10K_0402_5%  [R_0402]  110.78 29.84 270 top
R40  4.7K_0402_5%  [R_0402]  117.46 27.6 180 top
R41  100K_0402_5%  [R_0402]  123.67 27.59 90 top
R42  24.9K_0402_1%  [R_0402]  52.01 58.59 270 top
R43  7.15K_0402_1%  [R_0402]  52.9 58.59 270 top
R45  0_0402_5%  [R0402_0OHM]  53.79 56.81 270 top
R46  2.2K_0402_5%  [R_0402]  123.68 26.58 180 top
R47  2.2K_0402_5%  [R_0402]  119.35 27.59 90 top
R48  2.2K_0402_5%  [R_0402]  107.57 127.39 90 bottom
R49  2.2K_0402_5%  [R_0402]  103.77 128.13 180 bottom
R50  10K_0402_5%  [R_0402]  177.16 67.72 315 bottom
R57  10K_0402_5%  [R_0402]  218.86 58.54 270 top
R65  499K_0402_1%  [R_0402]  50.35 52.61 0 top
R66  100K_0402_5%  [R_0402]  52.56 48.55 0 top
R67  49.9K_0402_1%  [R_0402]  52.23 52.61 0 top
R68  200_0402_5%  [R_0402]  10.5 119.57 0 bottom
R69  200_0402_5%  [R_0402]  10.5 123.63 0 bottom
R72  100K_0402_5%  [R_0402]  211.06 46.44 0 top
R74  10K_0402_5%  [R_0402]  62.51 28.76 0 top
R75  100K_0402_5%  [R_0402]  56.68 30.93 270 top
R76  1M_0402_5%  [R_0402]  53.81 29.9 0 top
R77  0_0402_5%  [R0402_0OHM]  37.14 23.45 0 top
R78  0_0402_5%  [R_0402]  25.59 121.8 90 bottom
R79  100K_0402_5%  [R_0402]  30.46 121.39 180 bottom
R80  100K_0402_5%  [R_0402]  24.77 121.8 90 bottom
RA1  0_0805_5%  [R0805_0OHM]  32.93 1.75 90 top
RA2  0_0402_5%  [R0402_0OHM]  35.09 20.71 270 top
RA3  100K_0402_5%  [R_0402]  33.14 18.97 0 top
RA4  0_0603_5%  [R0603_0OHM]  21.05 24.19 270 top
RA5  0_0402_5%  [R0402_0OHM]  22.13 6.52 90 top
RA6  0_0402_5%  [R0402_0OHM]  23.14 6.47 0 top
RA7  33_0402_5%  [R_0402]  36.05 15.17 180 top
RA8  10K_0402_5%  [R_0402]  34.91 8.95 180 top
RA9  0_0402_5%  [R_0402]  35.42 11.82 0 top
RA10  200K_0402_1%  [R_0402]  34.05 18.14 180 top
RA11  0_0402_5%  [R_0402]  27.15 19.92 90 top
RA12  0_0402_5%  [R_0402]  26.39 19.92 90 top
RA13  BLM15PD800SN1D_2P  [MURAT_BLM15PD600SN1D_2P]  26.79 2.77 180 top
RA14  BLM15PD800SN1D_2P  [MURAT_BLM15PD600SN1D_2P]  26.79 3.92 180 top
RA15  BLM15PD800SN1D_2P  [MURAT_BLM15PD600SN1D_2P]  29.25 7.65 270 top
RA16  BLM15PD800SN1D_2P  [MURAT_BLM15PD600SN1D_2P]  30.39 7.65 270 top
RA17  0_0402_5%  [R0402_0OHM]  12.8 5.15 270 top
RA18  0_0402_5%  [R0402_0OHM]  11.97 5.15 270 top
RA22  0_0805_5%  [R0805_0OHM]  20.19 21.27 180 top
RA23  1K_0402_5%  [R_0402]  34.15 23.05 180 top
RA24  10K_0402_5%  [R_0402]  33.23 22.16 0 top
RA25  2.2K_0402_5%  [R_0402]  30.39 20.33 270 top
RA26  2.2K_0402_5%  [R_0402]  29.63 20.33 270 top
RA27  10_0402_1%  [R_0402]  24.37 12.38 180 top
RA28  1K_0402_5%  [R_0402]  22.18 19.36 0 top
RA29  4.7K_0402_5%  [R_0402]  24.37 13.14 180 top
RA30  10K_0402_5%  [R_0402]  18.14 14.35 180 bottom
RA31  10_0402_1%  [R_0402]  21.17 13.14 0 top
RA32  1K_0402_5%  [R_0402]  22.18 22.66 0 top
RA33  4.7K_0402_5%  [R_0402]  24.37 13.9 180 top
RA34  10K_0402_5%  [R_0402]  15.45 14.35 0 bottom
RA35  BLM15PX330SN1D_2P  [MURAT_BLM15PX330SN1D_2P]  31.28 19.45 90 top
RA36  0_0402_5%  [R0402_0OHM]  22.08 12.38 180 top
RA37  0_0402_5%  [R0402_0OHM]  22.08 13.9 180 top
RA38  BLM15PX330SN1D_2P  [MURAT_BLM15PX330SN1D_2P]  28.74 19.45 90 top
RA39  0_0603_5%  [R0603_0OHM]  15.78 13.71 90 top
RA40  0_0402_5%  [R0402_0OHM]  17.56 15.25 270 top
RA41  100K_0402_5%  [R_0402]  21.74 17.27 0 top
RA42  33_0402_5%  [R_0402]  36.31 10.09 180 top
RA43  33_0402_5%  [R_0402]  36.31 12.76 180 top
RC1  2.2K_0402_5%  [R_0402]  141.02 60.12 0 bottom
RC2  2.2K_0402_5%  [R_0402]  141.02 59.23 0 bottom
RC3  10K_0402_5%  [R_0402]  141.02 62.21 0 bottom
RC4  24.9_0402_1%  [R_0402]  133.48 88.43 90 top
RC5  100K_0402_5%  [R_0402]  130.14 63.6 270 top
RC6  100K_0402_5%  [R_0402]  129.4 39.94 180 bottom
RC7  100_0402_1%  [R_0402]  140.06 67.19 90 bottom
RC8  200_0402_1%  [R_0402]  118.43 59.51 90 top
RC9  100K_0402_5%  [R_0402]  102.02 119.45 270 top
RC10  121_0402_1%  [R_0402]  106.16 62.8 180 top
RC11  80.6_0402_1%  [R_0402]  106.16 64.57 180 top
RC12  100_0402_1%  [R_0402]  106.16 63.69 180 top
RC14  10K_0402_5%  [R_0402]  103.72 54.67 0 top
RC15  22_0402_5%  [R_0402]  109.6 61.76 270 bottom
RC17  0_0603_5%  [R0603_0OHM]  127.22 37.08 90 top
RC18  4.7K_0402_5%  [R_0402]  116.08 55.39 90 bottom
RC19  1K_0402_5%  [R_0402]  112.45 56.29 0 bottom
RC20  1K_0402_5%  [R_0402]  108.86 56 0 bottom
RC21  33_0402_5%  [R_0402]  117.62 42.92 0 bottom
RC22  1M_0402_1%  [R_0402]  142.76 55.56 270 bottom
RC23  33_0402_5%  [R_0402]  139.99 79.26 0 bottom
RC24  33_0402_5%  [R_0402]  139.99 78.37 0 bottom
RC25  33_0402_5%  [R_0402]  141.09 55.18 0 bottom
RC26  33_0402_5%  [R_0402]  141.09 56.07 0 bottom
RC27  2.2K_0402_5%  [R_0402]  127.83 54.81 90 top
RC28  2.2K_0402_5%  [R_0402]  132.02 55.22 270 top
RC33  1K_0402_5%  [R_0402]  127.13 57 270 bottom
RC34  1K_0402_5%  [R_0402]  128.02 57 270 bottom
RC35  10K_0402_5%  [R_0402]  135.43 54.92 90 bottom
RC36  10K_0402_5%  [R_0402]  125.35 54.12 90 bottom
RC37  2.2K_0402_5%  [R_0402]  128.13 54.76 0 bottom
RC38  4.7K_0402_5%  [R_0402]  128.91 57 270 bottom
RC39  150K_0402_5%  [R_0402]  122.68 56.3 270 top
RC40  1K_0402_1%  [R_0402]  110.71 55.35 90 bottom
RC41  1K_0402_1%  [R_0402]  114.14 55.42 90 bottom
RC42  10K_0402_5%  [R_0402]  126.24 54.12 90 bottom
RC44  4.7K_0402_5%  [R_0402]  108.7 59.97 0 bottom
RC45  10K_0402_5%  [R_0402]  123.64 56.3 270 bottom
RC46  10K_0402_5%  [R_0402]  132.97 56.36 270 bottom
RC47  10K_0402_5%  [R_0402]  123.64 56.3 270 top
RC51  10K_0402_5%  [R_0402]  124.7 58.48 180 top
RC52  10K_0402_5%  [R_0402]  123.78 57.72 0 top
RC53  10K_0402_5%  [R_0402]  103.72 53.78 0 top
RC54  10K_0402_5%  [R_0402]  104.63 52.89 180 top
RC55  10K_0402_5%  [R_0402]  127.13 54.12 90 bottom
RC56  10K_0402_5%  [R_0402]  126.18 57 270 bottom
RC57  10K_0402_5%  [R_0402]  123.54 41.58 90 top
RC58  10K_0402_5%  [R_0402]  124.4 42.46 270 top
RC63  10K_0402_5%  [R_0402]  148.21 55.77 90 top
RC64  10K_0402_5%  [R_0402]  148.2 57.56 0 top
RC65  100_0402_1%  [R_0402]  132.83 62.01 0 top
RC66  113_0402_1%  [R_0402]  126.54 63.05 270 top
RC67  1K_0402_5%  [R_0402]  122.3 56.81 270 bottom
RC68  1K_0402_5%  [R_0402]  121.41 56.81 270 bottom
RC69  10K_0402_5%  [R_0402]  133.77 58.17 270 top
RC72  10K_0402_5%  [R_0402]  104.63 52.07 0 top
RC73  10K_0402_5%  [R_0402]  104.63 51.18 0 top
RC74  0_0402_5%  [R_0402]  94.45 37.27 0 bottom
RC75  0_0402_5%  [R_0402]  94.45 36.38 0 bottom
RC76  2.71K_0402_1%  [R_0402]  139.78 82.38 270 bottom
RC77  20K_0402_5%  [R_0402]  86.29 39.25 0 bottom
RC78  20K_0402_5%  [R_0402]  92.49 38.57 180 bottom
RC80  1M_0402_1%  [R_0402]  141.69 78.28 90 bottom
RC82  10M_0402_5%  [R_0402]  104.07 59.59 0 top
RC85  10K_0402_5%  [R_0402]  120.58 66.45 90 top
RC86  10K_0402_5%  [R_0402]  141.94 60.92 180 bottom
RC87  100K_0402_5%  [R_0402]  110.73 70.29 180 bottom
RC88  10K_0402_5%  [R_0402]  117.46 66.23 180 top
RC89  8.2K_0402_5%  [R_0402]  102.14 53.67 270 top
RC90  10K_0402_5%  [R_0402]  101.25 53.67 270 top
RC91  1M_0402_5%  [R_0402]  102.84 61.45 90 top
RC92  10K_0402_5%  [R_0402]  119.92 41.58 90 top
RC93  100K_0402_5%  [R_0402]  99.48 42.36 270 bottom
RC94  10K_0402_5%  [R_0402]  99.14 58.35 0 top
RC95  1K_0402_5%  [R_0402]  139.51 104.24 180 bottom
RC96  60.4_0402_1%  [R_0402]  140.67 99.34 180 bottom
RC97  0_0402_5%  [R0402_0OHM]  111.6 69.45 90 bottom
RC99  0_0402_5%  [R0402_0OHM]  98.46 41.45 90 bottom
RC102  1M_0402_5%  [R_0402]  99.46 52.7 0 top
RC103  10K_0402_1%  [R_0402]  120.3 40.39 270 top
RC104  1K_0402_5%  [R_0402]  144.31 100.27 270 top
RC105  10K_0402_5%  [R_0402]  146.37 106.78 270 top
RC106  0_0402_5%  [R0402_0OHM]  144.59 106.78 270 top
RC107  0_0402_5%  [R0402_0OHM]  145.48 105.87 90 top
RC108  0_0402_5%  [R_0402]  117.88 44.33 90 bottom
RC109  100K_0402_5%  [R_0402]  118 46.11 90 bottom
RC110  1K_0402_5%  [R_0402]  95.36 38.16 180 bottom
RC111  49.9_0402_1%  [R_0402]  140.48 94.07 180 bottom
RC112  1K_0402_5%  [R_0402]  141.26 93.99 0 bottom
RC113  1K_0402_5%  [R_0402]  142.31 98.63 90 bottom
RC114  10K_0402_5%  [R_0402]  104.73 48.95 0 top
RC115  10K_0402_5%  [R_0402]  108.71 58.14 270 bottom
RC117  499_0402_1%  [R_0402]  140.67 98.45 180 bottom
RC118  0_0402_5%  [R_0402]  109.6 57.23 90 bottom
RC119  49.9_0402_1%  [R_0402]  106.16 61.02 180 top
RC120  49.9_0402_1%  [R_0402]  106.16 61.84 180 top
RC121  49.9_0402_1%  [R_0402]  132.01 98.51 0 top
RC122  49.9_0402_1%  [R_0402]  131.61 96.78 270 top
RC123  33_0402_5%  [R_0402]  93.95 51.54 90 top
RC124  33_0402_5%  [R_0402]  96.05 51.54 90 top
RC125  33_0402_5%  [R_0402]  93.38 48.69 90 top
RC126  1K_0402_5%  [R_0402]  94.27 48.69 90 top
RC127  33_0402_5%  [R_0402]  93.06 51.54 90 top
RC128  8.2K_0402_5%  [R_0402]  108.7 59.08 0 bottom
RC129  4.7K_0402_5%  [R_0402]  95.16 48.69 90 top
RC130  200_0402_1%  [R_0402]  125.31 61.38 0 top
RC131  10K_0402_1%  [R_0402]  141.46 100.64 180 bottom
RC132  10K_0402_1%  [R_0402]  141.46 101.43 180 bottom
RC133  10K_0402_1%  [R_0402]  137.68 104.28 270 bottom
RC134  49.9_0402_1%  [R_0402]  132.63 94.67 180 top
RC136  10K_0402_1%  [R_0402]  133.42 100.72 90 top
RC137  0_0402_5%  [R_0402]  124.34 66.02 0 top
RC138  100K_0402_5%  [R_0402]  142.45 97.5 180 bottom
RC139  1K_0402_5%  [R_0402]  111.54 56.27 270 bottom
RC140  51_0402_5%  [R_0402]  141.4 92.56 0 bottom
RC141  51_0402_5%  [R_0402]  144.31 97.65 90 top
RC142  51_0402_5%  [R_0402]  140.48 89.66 0 bottom
RC143  1K_0402_5%  [R_0402]  141.94 63.09 180 bottom
RC144  0_0402_5%  [R_0402]  141.24 103.4 180 bottom
RC145  0_0402_5%  [R_0402]  113.36 55.4 180 bottom
RC146  51_0402_1%  [R_0402]  139.56 93.18 0 bottom
RC147  51_0402_5%  [R_0402]  141.37 90.99 0 bottom
RC148  1K_0402_5%  [R_0402]  100.05 59.29 90 top
RC149  0_0603_5%  [R_0603]  146.18 61.27 180 bottom
RC150  100_0402_1%  [R_0402]  147.1 82.24 270 top
RC151  100_0402_1%  [R_0402]  147.1 80.46 270 top
RC152  56_0402_1%  [R_0402]  142.45 95.85 180 bottom
RC153  220_0402_5%  [R_0402]  139.76 95.85 0 bottom
RC154  100_0402_1%  [R_0402]  140.67 97.5 180 bottom
RC155  100_0402_1%  [R_0402]  132.46 101.39 90 top
RC156  100_0402_1%  [R_0402]  131.57 102.44 90 top
RC157  0_0402_5%  [R_0402]  132.08 88.6 90 top
RC159  100_0402_1%  [R_0402]  145.79 71.19 180 top
RC160  100_0402_1%  [R_0402]  144.89 72.05 0 top
RC163  0_0402_5%  [R_0402]  121.57 58.28 90 top
RC164  10K_0402_5%  [R_0402]  86.98 35.64 90 bottom
RC169  0_0603_5%  [R0603_0OHM]  143.75 58.47 90 bottom
RC170  0_0603_5%  [R0603_0OHM]  149.93 70.83 180 top
RC171  0_0603_5%  [R0603_0OHM]  148.18 76.32 180 top
RC173  0_0603_5%  [R0603_0OHM]  149.35 71.4 180 bottom
RC174  0_0603_5%  [R0603_0OHM]  147.68 59.48 270 bottom
RC175  0_0402_5%  [R_0402]  140.32 104.24 0 bottom
RC176  15_0402_5%  [R_0402]  123.88 46.7 0 bottom
RC177  15_0402_5%  [R_0402]  119.94 41.17 0 bottom
RC178  15_0402_5%  [R_0402]  120.86 43.23 180 bottom
RC179  15_0402_5%  [R_0402]  120.86 42.13 180 bottom
RC180  15_0402_5%  [R_0402]  126.57 46.7 180 bottom
RC181  10K_0402_5%  [R_0402]  122.64 41.69 180 top
RC182  10K_0402_5%  [R_0402]  120.94 42.49 270 top
RC188  10K_0402_5%  [R_0402]  104.63 50.29 0 top
RC194  10K_0402_5%  [R_0402]  195 61.73 0 top
RC195  100K_0402_5%  [R_0402]  212.43 33.59 0 top
RC196  100K_0402_5%  [R_0402]  212.43 34.48 0 top
RC197  0_0402_5%  [R_0402]  117.57 42.49 270 top
RC198  0_0402_5%  [R_0402]  113.24 104.58 0 bottom
RC199  0_0402_5%  [R_0402]  109.52 67.5 180 bottom
RC205  10K_0402_5%  [R_0402]  128.58 58.25 0 top
RC207  10K_0402_5%  [R_0402]  127.19 61.27 270 top
RC209  10K_0402_5%  [R_0402]  136.2 54.92 0 bottom
RC211  100K_0402_5%  [R_0402]  101.25 54.64 90 top
RC212  2.2K_0402_5%  [R_0402]  127.97 61.27 270 top
RC213  100K_0402_5%  [R_0402]  220.48 32.52 0 bottom
RC224  10K_0402_5%  [R_0402]  44.98 58.5 90 top
RC443  0_0402_5%  [R_0402]  117.93 92.1 0 top
RD1  0_0402_5%  [R_0402]  75.96 46.85 180 top
RD2  0_0402_5%  [R_0402]  71.17 44.76 0 top
RD3  0_0402_5%  [R_0402]  70.47 67.17 0 top
RD4  0_0402_5%  [R0402_0OHM]  74.18 46.85 180 top
RD5  0_0402_5%  [R0402_0OHM]  72.95 44.76 0 top
RD6  0_0402_5%  [R0402_0OHM]  71.39 68.06 180 top
RD7  470_0402_1%  [R_0402]  61.57 88.44 90 top
RD8  0_0402_5%  [R0402_0OHM]  62.39 89.35 270 top
RD9  2_0402_1%  [R_0402]  68.63 68.51 0 top
RD10  1K_0402_1%~D  [R_0402]  68.03 71.18 0 top
RD11  24.9_0402_1%  [R_0402]  66.74 69.41 270 top
RD12  1K_0402_1%~D  [R_0402]  70.49 69.85 270 top
RD13  0_0402_5%  [R_0402]  63.1 46.73 180 top
RD14  0_0402_5%  [R0402_0OHM]  59.69 44.43 90 top
RD15  0_0402_5%  [R_0402]  57.86 67.94 0 top
RD16  0_0402_5%  [R0402_0OHM]  61.42 46.73 180 top
RD17  0_0402_5%  [R_0402]  60.58 45.34 270 top
RD18  0_0402_5%  [R0402_0OHM]  58.77 67.06 180 top
RD19  2_0402_1%  [R_0402]  58.47 70.92 0 top
RD20  1K_0402_1%~D  [R_0402]  58.47 71.81 0 top
RD21  1K_0402_1%~D  [R_0402]  59.39 70.03 180 top
RD22  24.9_0402_1%  [R_0402]  57.6 69.79 270 top
RD23  240_0402_1%  [R_0402]  70.19 78.93 0 top
RD24  240_0402_1%  [R_0402]  57.69 81.8 270 top
RE1  100K_0402_1%  [R_0402]  42.42 84.18 270 top
RE2  0_0603_5%  [R0603_0OHM]  43.56 87.59 270 top
RE3  100K_0402_1%  [R_0402]  45.15 80.49 270 top
RE4  100K_0402_1%  [R_0402]  43.27 80.58 0 top
RE6  100K_0402_1%  [R_0402]  43.3 82.35 180 top
RE7  0_0603_5%  [R0603_0OHM]  39.12 82.13 270 top
RE8  4.7K_0402_5%  [R_0402]  31.64 73.69 180 top
RE9  4.7K_0402_5%  [R_0402]  28.56 73.69 0 top
RE10  2.2K_0402_5%  [R_0402]  31.64 72.48 180 top
RE11  2.2K_0402_5%  [R_0402]  28.56 72.48 0 top
RE12  1K_0402_5%  [R_0402]  30.31 75.88 0 top
RE13  10K_0402_5%  [R_0402]  37.4 58.12 90 top
RE14  100K_0402_5%  [R_0402]  33.59 59.67 270 top
RE15  100K_0402_5%  [R_0402]  52 62.83 0 top
RE16  10K_0402_5%  [R_0402]  52 63.72 0 top
RE17  100K_0402_5%  [R_0402]  28.51 71.35 270 top
RE18  100K_0402_5%  [R_0402]  31.23 77.66 180 top
RE19  1K_0402_5%  [R_0402]  52.31 68.35 0 top
RE20  10K_0402_5%  [R_0402]  31.1 63.43 180 top
RE21  100K_0402_5%  [R_0402]  31.23 76.77 180 top
RE23  43_0402_1%  [R_0402]  52.06 77.5 0 top
RE25  100K_0402_5%  [R_0402]  52.9 61.95 270 top
RE28  0_0402_5%  [R0402_0OHM]  45.53 83.64 90 top
RE29  1K_0402_5%  [R_0402]  39.75 83.26 90 top
RE32  100K_0402_5%  [R_0402]  40.64 83.26 90 top
RE37  0_0402_5%  [R0402_0OHM]  52.82 70.13 0 top
RE40  10K_0402_5%  [R_0402]  38.9 84.18 90 top
RE41  100K_0402_5%  [R_0402]  32.7 80.68 270 top
RE42  0_0402_5%  [R0402_0OHM]  41.12 57.77 90 top
RE43  100_0402_5%  [R_0402]  31.82 79.77 90 top
RE45  0_0402_5%  [R_0402]  35.96 79.78 180 top
RE46  10K_0402_1%  [R_0402]  29.34 64.47 90 top
RE47  0_0402_5%  [R0402_0OHM]  36.83 79.77 90 top
RE48  10K_0402_1%  [R_0402]  30.23 65.38 270 top
RE49  100K_0402_5%  [R_0402]  53.74 71.02 180 top
RE50  0_0603_5%  [R0603_0OHM]  44.39 84.67 270 top
RE51  300_0402_5%  [R_0402]  45.15 81.42 90 top
RE52  100K_0402_5%  [R_0402]  51.95 70.12 90 top
RE53  100K_0402_5%  [R_0402]  49.61 56.48 180 top
RE54  300_0402_5%  [R_0402]  41.47 80.6 90 top
RE55  10K_0402_5%  [R_0402]  43.12 91.2 90 top
RE56  100K_0402_5%  [R_0402]  43.07 89.88 180 top
RE57  10K_0402_5%  [R_0402]  41.28 91.2 90 top
RE58  10K_0402_5%  [R_0402]  40.39 91.2 90 top
RE59  49.9_0402_1%  [R_0402]  48.66 92.67 180 top
RE60  0_0402_5%  [R0402_0OHM]  48.64 91.61 270 top
RE61  0_0402_5%  [R0402_0OHM]  47.75 91.61 270 top
RE62  10K_0402_5%  [R_0402]  42.17 92.12 270 top
RE63  0_0402_5%  [R0402_0OHM]  44.01 92.12 270 top
RE65  0_0402_5%  [R_0402]  113.06 29.57 90 bottom
RE66  0_0603_5%  [R0603_0OHM]  43.06 58 90 top
RE67  33_0402_5%  [R_0402]  45.75 58.51 90 top
RE68  10K_0402_5%  [R_0402]  31.1 62.54 180 top
RE70  100K_0402_5%  [R_0402]  33.61 81.94 180 top
RE81  0_0402_5%  [R0402_0OHM]  30.9 79.74 90 top
RE91  0_0402_5%  [R_0402]  53.48 47.76 180 top
RE92  0_0402_5%  [R_0402]  53.48 47 180 top
RH1  100K_0402_1%_B25/50 4250K  [R_0402]  124.88 53.98 270 top
RI1  5.6_0402_1%  [R_0402]  17.95 99.48 180 bottom
RI2  5.6_0402_1%  [R_0402]  17.95 100.37 180 bottom
RI3  150_0402_5%  [R_0402]  15.59 100.38 270 bottom
RI4  5.6_0402_1%  [R_0402]  17.95 102.21 180 bottom
RI5  5.6_0402_1%  [R_0402]  17.95 101.32 180 bottom
RI6  150_0402_5%  [R_0402]  15.59 102.22 270 bottom
RI7  5.6_0402_1%  [R_0402]  17.95 95.79 180 bottom
RI8  5.6_0402_1%  [R_0402]  17.95 96.68 180 bottom
RI9  150_0402_5%  [R_0402]  15.59 96.7 270 bottom
RI10  5.6_0402_1%  [R_0402]  17.95 97.64 180 bottom
RI11  5.6_0402_1%  [R_0402]  17.95 98.52 180 bottom
RI12  150_0402_5%  [R_0402]  15.59 98.54 270 bottom
RI13  2.2K_0402_5%  [R_0402]  25.64 107.73 180 bottom
RI14  2.2K_0402_5%  [R_0402]  22.88 107.73 0 bottom
RI15  1M_0402_5%  [R_0402]  20.91 107.73 0 bottom
RI16  20K_0402_5%  [R_0402]  19.69 104.44 90 bottom
RL1  0_0603_5%  [R_0603]  19.47 90.42 90 top
RL2  2.49K_0402_1%~D  [R_0402]  19.26 82.88 0 top
RL3  1K_0402_5%  [R_0402]  27.21 90.94 270 top
RL4  15K_0402_1%  [R_0402]  26.32 90.03 90 top
RL5  0_0603_5%  [R0603_0OHM]  21.75 91.94 270 top
RL6  100K_0402_5%  [R_0402]  27.8 101.66 180 top
RL7  10K_0402_5%  [R_0402]  25.1 101.66 0 top
RL8  33_0402_5%  [R_0402]  19.2 86.76 0 top
RL9  33_0402_5%  [R_0402]  19.2 85.87 0 top
RL13  0_0402_5%  [R0402_0OHM]  29.07 85.53 180 bottom
RL14  75_0603_5%  [R_0603]  19.85 77.47 270 top
RL15  75_0603_5%  [R_0603]  18.58 77.47 270 top
RL17  10K_0402_5%  [R_0402]  21.43 85.2 90 bottom
RL19  75_0603_5%  [R_0603]  18.58 77.47 270 bottom
RL20  75_0603_5%  [R_0603]  19.85 77.47 270 bottom
RM1  0_0603_5%  [R_0603]  146.07 41.02 270 bottom
RM2  0_0603_5%  [R_0603]  156.12 38.73 270 top
RM3  20K_0402_5%  [R_0402]  150.28 34.02 90 bottom
RM12  20K_0402_5%  [R_0402]  147.75 37.45 0 bottom
RM13  20K_0402_5%  [R_0402]  151.08 38.51 180 bottom
RM14  10_0402_1%  [R_0402]  149.21 41.08 270 bottom
RM15  10_0402_1%  [R_0402]  149.51 34.02 90 bottom
RM16  10_0402_1%  [R_0402]  137.91 36.54 0 bottom
RM17  10_0402_1%  [R_0402]  139.82 37.49 0 bottom
RM18  10_0402_1%  [R_0402]  139.82 36.54 0 bottom
RM19  10_0402_1%  [R_0402]  137.91 37.49 0 bottom
RM20  10_0402_1%  [R_0402]  137.91 38.44 0 bottom
RM21  10_0402_1%  [R_0402]  139.82 38.44 0 bottom
RM22  10_0402_1%  [R_0402]  139.82 39.4 0 bottom
RM23  10_0402_1%  [R_0402]  137.91 39.4 0 bottom
RM24  10_0402_1%  [R_0402]  148.67 39.26 270 bottom
RM25  0_0402_5%  [R_0402]  148.72 33.99 90 bottom
RM27  10K_0402_5%  [R_0402]  146.78 33.07 90 bottom
RP1  100K_8P4R_5%  [RP_0804_8P4R]  216.19 52.89 180 top
RP2  100_8P4R_5%  [RP_0804_8P4R]  215.04 51.4 0 top
RPC1  10K_8P4R_5%  [RP_0804_8P4R]  143.98 63.7 0 bottom
RPC2  15_0804_8P4R_5%  [RP_0804_8P4R]  110.05 65.48 180 bottom
RPC3  1K_0804_8P4R_1%  [RP_0804_8P4R]  130.19 56.04 270 bottom
RPE1  10K_8P4R_5%  [RP_0804_8P4R]  51.43 81.42 0 top
RPE2  10K_8P4R_5%  [RP_0804_8P4R]  48.26 81.42 0 top
RPE3  100K_8P4R_5%  [RP_0804_8P4R]  29.84 70.94 0 top
RPE4  100K_8P4R_5%  [RP_0804_8P4R]  34.75 57.49 90 top
RPE5  100K_8P4R_5%  [RP_0804_8P4R]  53.54 65.7 180 top
RPE6  100K_8P4R_5%  [RP_0804_8P4R]  53.6 72.17 180 top
RPE7  10K_0804_8P4R_5%  [RP_0804_8P4R]  46.6 92.11 270 top
RPI1  470_8P4R_5%  [RP_0804_8P4R]  16.41 97.94 0 top
RPI2  470_8P4R_5%  [RP_0804_8P4R]  16.41 101.62 0 top
RPM1  20K_0804_8P4R_1%  [RP_0804_8P4R]  138.17 36.46 0 top
RPM2  20K_0804_8P4R_1%  [RP_0804_8P4R]  138.17 39.32 0 top
RS1  0_0402_5%  [R0402_0OHM]  186.85 35.42 90 top
RS2  10K_0402_5%  [R_0402]  21.9 30.23 0 top
RS3  100K_0402_5%  [R_0402]  191.04 36.33 270 top
RS4  100K_0402_5%  [R_0402]  185.96 36.33 270 top
RS5  10K_0402_5%  [R_0402]  178.72 41.41 270 bottom
RU1  0_0402_5%  [R_0402-NPM]  24.29 48.34 180 bottom
RU2  0_0402_5%  [R_0402-NPM]  24.29 47.45 180 bottom
RU3  0_0402_5%  [R_0402]  21.1 55.07 0 bottom
RU4  0_0402_5%  [R_0402]  21.1 54.18 0 bottom
RU5  0_0402_5%  [R_0402]  21.1 53.29 0 bottom
RU6  0_0402_5%  [R_0402]  21.1 52.4 0 bottom
RU7  0_0402_5%  [R_0402-NPM]  24.02 33.26 180 top
RU8  0_0402_5%  [R_0402-NPM]  24.02 32.37 180 top
RU9  0_0402_5%  [R_0402]  22.59 38.49 0 bottom
RU10  0_0402_5%  [R_0402]  22.59 37.6 0 bottom
RU11  0_0402_5%  [R_0402]  22.59 36.71 0 bottom
RU12  0_0402_5%  [R_0402]  22.59 35.82 0 bottom
RU13  0_0402_5%  [R_0402-NPM]  208.19 40.06 270 bottom
RU14  0_0402_5%  [R_0402-NPM]  209.14 40.06 270 bottom
RU15  0_0402_5%  [R_0402-NPM]  206.41 40.06 270 bottom
RU16  0_0402_5%  [R_0402-NPM]  207.3 40.06 270 bottom
RW3  0_0805_5%  [R_0805]  69.54 123.76 0 top
